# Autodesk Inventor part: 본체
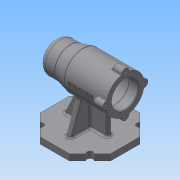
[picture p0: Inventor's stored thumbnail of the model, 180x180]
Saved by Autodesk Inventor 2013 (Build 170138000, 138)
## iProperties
Created: 2019-12
Part Number: 본체
Material: 일반
Document SubType Name: Modeling
Designer: Administrator
Density: 1 g/cm^3
Author: Administrator
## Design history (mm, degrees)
sketch "스케치1"
  geometry: L1 (-56, 0)-(56, 0); L2 (-56, 0)-(-56, 25); L3 (-56, 25)-(-31, 25); L4 (56, 30)-(56, 0); L5 (-31, 25)-(-11, 30); L6 (-11, 30)-(56, 30); 2 further points
  constraints: 12 end point, 3 perpendicular, 1 coincident, 1 horizontal, 1 midpoint, 1 parallel
  dimensions: "d0" = 112 distance of L1.start L1.end; "d2" = 50 diameter of L3 L1; "d3" = 60 diameter of L6 L1; "d4" = 25 distance of L2.end L3.end; "d5" = 45 distance from line of L2 L5.end
revolve "회전1" sketch "스케치1" stored, may be unused: angle "d6" = 90 deg
node "작업 평면1"
sketch "스케치8" dims "d26" = 112
  geometry: L1 (23.196, 56)-(56, 23.196); L2 (56, 23.196)-(56, -23.196); L3 (56, -23.196)-(23.196, -56); L4 (23.196, -56)-(-23.196, -56); L5 (-23.196, -56)-(-56, -23.196); L6 (-56, -23.196)-(-56, 23.196); L7 (-56, 23.196)-(-23.196, 56); L8 (-23.196, 56)-(23.196, 56); 4 further points
  constraints: 16 end point, 2 coincident, 2 vertical alignment, 1 midpoint, 19 other
extrude "돌출7" join sketch "스케치8" distance "d27" = 10; taper "d28" = 0 deg
sketch "스케치9"
  geometry: L1 (-56, -80)-(-56, -70) reference; L2 (-23.196, -70)-(-56, -70) reference; L3 (56, -80)-(56, -70) reference; L4 (56, -70)-(23.196, -70) reference; L5 (-31, -25)-(-11, -30) reference; L6 (-11, -30)-(56, -30) reference; L7 (-56, -70)-(-38, -70); L8 (-38, -70)-(-12.643, -15.622); L9 (56, -70)-(31, -70); L10 (31, -70)-(31, -15); L11 (31, -15)-(-12.643, -15.622); L12 (-38, -70)-(31, -70); 1 further point
  constraints: 12 end point, 2 point on line, 1 collinear, 1 perpendicular
  dimensions: "d29" = 18 distance of L1.end L7.end; "d30" = 60 distance of L7.end L8.end; "d31" = 115 deg angle of L8 L7; "d32" = 25 distance of L3.end L9.end; "d33" = 55 distance of L9.end L10.end
extrude "돌출8" join sketch "스케치9" stored distance "d34" = 8; taper "d35" = 0 deg
sketch "스케치10"
  geometry: L1 (-70, 56)-(-70, 23.196) reference; L2 (-70, -23.196)-(-70, -56) reference; L3 (-80, 56)-(-70, 56) reference; L4 (-70, 56)-(-70, 36); L5 (-70, 36)-(-18.317, 17.189); L6 (-70, 36)-(-15, 36); L7 (-70, -56)-(-70, -36); L8 (-70, -36)-(-20.364, -17.934); L9 (-70, 36)-(-70, -36); A1 r 30 centre (0, 0) between (-29.732, -4) and (-29.732, 4) reference; A2 r 30 centre (0, 0) between (-23.234, 18.979) and (-23.234, -18.979); 1 further point
  constraints: 12 end point, 4 point on line, 3 point on circle, 1 centre point, 1 coincident, 1 collinear, 1 equal length, 1 horizontal
  dimensions: "d36" = 20 distance of L1.start L4.end; "d37" = 55 distance of L4.end L5.end; "d38" = 20 deg angle of L5 L6; "d39" = 20 distance of L2.end L7.end; "d40" = 110 deg angle of L7 L8; "d41" = 52.82159 distance of L7.end L8.end
extrude "돌출9" join sketch "스케치10" stored distance "d42" = 8; taper "d43" = 0 deg
sketch "스케치2"
  geometry: C1 r 30 at (0, 0) reference; C2 r 21 at (0, 0)
  constraints: 1 centre point, 1 coincident
  dimensions: "d7" = 42 diameter of C2
extrude "돌출1" cut sketch "스케치2" distance "d8" = 15; taper "d9" = 0 deg
sketch "스케치3"
  geometry: C1 r 21 at (0, 0) reference; C2 r 24 at (0, 0)
  constraints: 1 centre point, 1 coincident
  dimensions: "d10" = 48 diameter of C2
extrude "돌출2" cut sketch "스케치3" distance "d11" = 54; taper "d12" = 0 deg
sketch "스케치4"
  geometry: C1 r 24 at (0, 0) reference; C2 r 21 at (0, 0)
  constraints: 1 centre point, 1 coincident
  dimensions: "d13" = 42 diameter of C2
extrude "돌출3" cut sketch "스케치4" distance "d14" = 12; taper "d15" = 0 deg
sketch "스케치5"
  geometry: C1 r 21 at (0, 0) reference; C2 r 17.5 at (0, 0)
  constraints: 1 centre point, 1 coincident
  dimensions: "d16" = 35 diameter of C2
extrude "돌출4" cut sketch "스케치5" distance "d17" = 18; taper "d18" = 0 deg
sketch "스케치6"
  geometry: C1 r 17.5 at (0, 0) reference; C2 r 16 at (0, 0)
  constraints: 1 centre point, 1 coincident
  dimensions: "d19" = 32 diameter of C2
extrude "돌출5" cut sketch "스케치6" distance "d20" = 4; taper "d21" = 0 deg
sketch "스케치7"
  geometry: C1 r 16 at (0, 0) reference; C2 r 10.5 at (0, 0)
  constraints: 1 centre point, 1 coincident
  dimensions: "d22" = 21 diameter of C2
extrude "돌출6" cut sketch "스케치7" distance "d23" = 3; taper "d24" = 0 deg
sketch "스케치11"
  geometry: L1 (0, 0)-(0, 30); C1 r 6 at (0, 30); 1 further point
  constraints: 2 coincident, 2 end point, 2 vertical alignment, 1 centre point, 3 other
  dimensions: "d44" = 30 distance of L1.start L1.end; "d46" = 12 diameter of C1
extrude "돌출10" join sketch "스케치11" distance "d47" = 16; taper "d48" = 0 deg
sketch "스케치12"
  geometry: A1 r 6 centre (0, 0) between (5.97, -0.6) and (-5.97, -0.6) reference; 1 further point
  constraints: 1 coincident
hole "구멍1" sketch "스케치12" at (0, 0) diameter "d49" = 3.242; stored, may be unused: countersink angle "d53" = 82 deg, drill point angle "d55" = 118 deg; dims "d50" = 8, "d51" = 3.023, "d52" = 2, "d54" = 11
fillet "모깎기2" dims "d59" = 0.3, "d60" = 3
fillet "모깎기3" dims "d64" = 3, "d65" = 10
fillet "모깎기4" dims "d66" = 1, "d67" = 3
fillet "모깎기5" dims "d68" = 3
sketch "스케치13"
  geometry: L1 (23.196, -56)-(56, -23.196) reference; L2 (56, 23.196)-(23.196, 56) reference; L3 (-23.196, 56)-(-56, 23.196) reference; L4 (-56, -23.196)-(-23.196, -56) reference; L5 (0, 0)-(-39.598, 39.598); L6 (0, 0)-(39.598, 39.598); L7 (0, 0)-(39.598, -39.598); L8 (0, 0)-(-39.598, -39.598); C1 r 5 at (-39.598, 39.598); C2 r 5 at (39.598, 39.598); C3 r 5 at (39.598, -39.598); C4 r 5 at (-39.598, -39.598)
  constraints: 8 end point, 4 centre point, 4 coincident, 4 midpoint, 1 perpendicular
  dimensions: "d69" = 10 diameter of C1; "d70" = 10 diameter of C2; "d71" = 10 diameter of C3; "d72" = 10 diameter of C4
extrude "돌출11" cut sketch "스케치13" distance "d73" = 10; taper "d74" = 0 deg
node "작업 평면2"
sketch "스케치14"
  geometry: L1 (33.5, 6.771)-(33.5, 29.226) reference; 2 further points
  constraints: 1 horizontal alignment, 1 other
  dimensions: "d75" = 41 distance from line of L1 point (-7.5, 0)
feature "엠보싱1" sketch "스케치14" dims "d0" = 112, "d2" = 50, "d3" = 60, "d4" = 25, "d5" = 45, "d76" = 0.5, "d77" = 0
chamfer "모따기1" distance "d78" = 1; stored, may be unused: second distance "d79" = 2, angle "d80" = 45 deg
node "솔리드1"
pattern_circular "원형 패턴1" dims angle "d62" = 360 deg
